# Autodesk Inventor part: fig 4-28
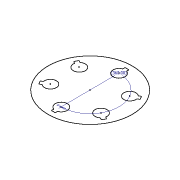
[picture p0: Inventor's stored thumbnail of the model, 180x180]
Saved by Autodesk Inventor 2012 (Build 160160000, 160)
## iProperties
Created: 2004-05
Part Number: fig 4-28
Document SubType Name: Modeling
Designer: CADCIM Technologies
Manufacturer: Standard
Standards Organization: Custom
Density: 1 g/cm^3
Material: Default
Author: CADCIM Technologies
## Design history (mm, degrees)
sketch "Sketch1"
  geometry: L1 (45.774, 51.065)-(45.774, 52.473); L2 (45.774, 52.473)-(43.425, 52.473); L3 (43.425, 52.473)-(43.425, 51.065); L4 (27.029, 41.48)-(25.81, 42.184); L5 (25.81, 42.184)-(24.635, 40.149); L6 (24.635, 40.149)-(25.855, 39.445); L7 (25.958, 20.454)-(24.739, 19.75); L8 (24.739, 19.75)-(25.914, 17.715); L9 (25.914, 17.715)-(27.133, 18.419); L10 (43.631, 9.012)-(43.631, 7.605); L11 (43.631, 7.605)-(45.981, 7.605); L12 (45.981, 7.605)-(45.981, 9.012); L13 (62.376, 18.598)-(63.595, 17.894); L14 (63.595, 17.894)-(64.77, 19.929); L15 (64.77, 19.929)-(63.551, 20.632); L16 (63.448, 39.624)-(64.667, 40.328); L17 (64.667, 40.328)-(63.492, 42.363); L18 (63.492, 42.363)-(62.273, 41.659); C1 r 25.482 at (44.703, 30.039); A1 r 3.618 centre (44.6, 47.644) between (43.425, 51.065) and (45.774, 51.065); A2 r 3.618 centre (29.405, 38.752) between (25.855, 39.445) and (27.029, 41.48); A3 r 3.618 centre (29.508, 21.147) between (27.133, 18.419) and (25.958, 20.454); A4 r 3.618 centre (44.806, 12.434) between (45.981, 9.012) and (43.631, 9.012); A5 r 3.618 centre (60.001, 21.326) between (63.551, 20.632) and (62.376, 18.598); A6 r 3.618 centre (59.897, 38.931) between (62.273, 41.659) and (63.448, 39.624)
  constraints: 36 end point, 12 point on circle, 7 centre point, 1 horizontal alignment, 1 parallel, 55 other
  dimensions: "d2" = 360 deg dimension on C1.centre A1.centre (derived)
